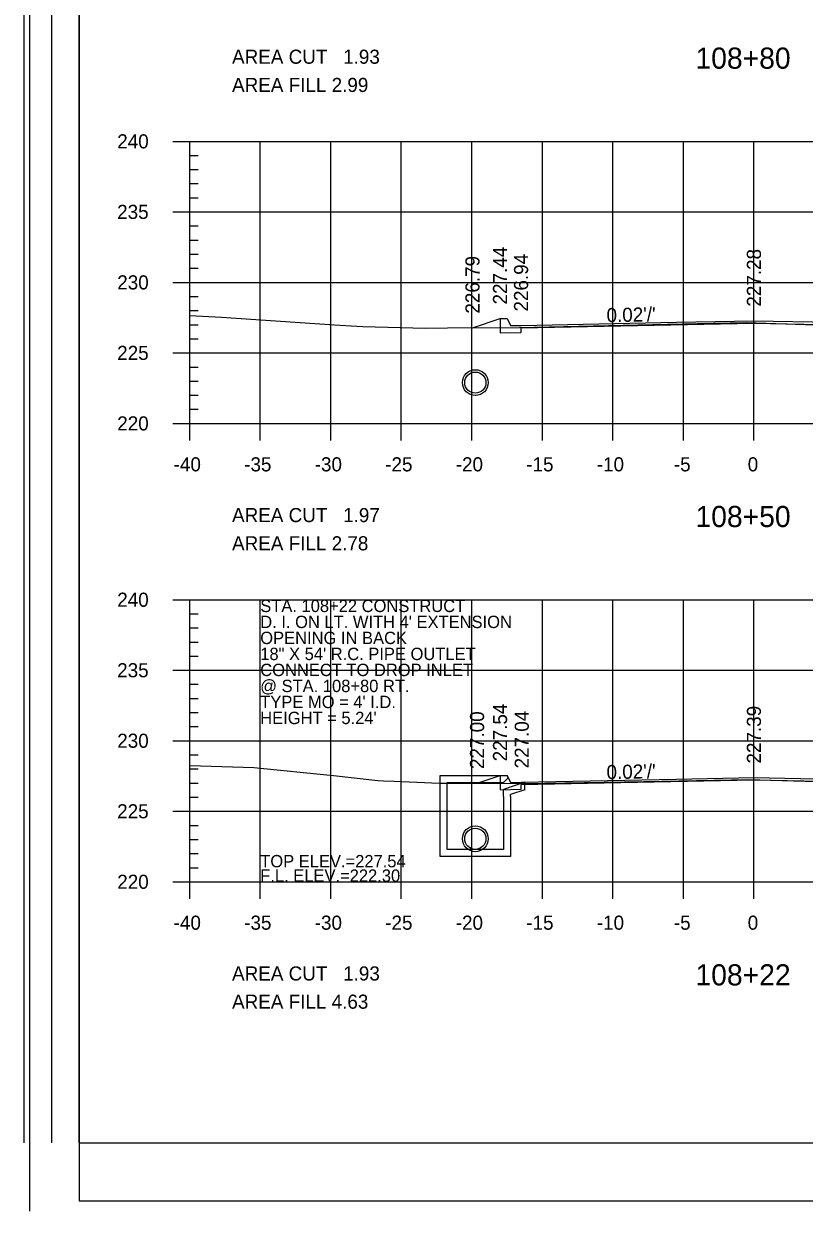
# Model space of a CAD drawing. Extents: x 1367903 to 1373764, y 376865 to 382130.
# Drawn here: x 1371878.7 to 1371989.4, y 377279.1 to 377447.5 of the extents above; entities that cross this region are included whole.
import ezdxf

# ---------------------------------------------------------------- set-up
doc = ezdxf.new("R2010")
doc.units = 0
for name, color, linetype in [('R_Axis', 7, 'Continuous'), ('R_Axis Annot', 7, 'Continuous'), ('R_Border', 7, 'Continuous'), ('R_Border PE', 7, 'Continuous'), ('R_Draft', 7, 'Continuous'), ('R_Exist Surface', 7, 'Continuous'), ('R_Fin Surface', 7, 'Continuous'), ('R_Fin Surface Annot', 7, 'Continuous'), ('R_Grid', 7, 'Continuous'), ('R_Water', 7, 'Continuous'), ('R_Water Annot', 7, 'Continuous')]:
    doc.layers.add(name, color=color, linetype=linetype)

msp = doc.modelspace()

# ---------------------------------------------------------------- linework, layer by layer
for p, q in [((1371937.78, 377340.92), (1371947.28, 377340.92)), ((1371937.78, 377337.92), (1371937.78, 377340.92)), ((1371938.78, 377337.92), (1371938.78, 377339.92)), ((1371938.78, 377339.92), (1371946.78, 377339.92)), ((1371947.44, 377340.59), (1371946.78, 377339.92)), ((1371949.78, 377339.96), (1371946.78, 377338.92)), ((1371947.44, 377340.59), (1371947.28, 377340.92)), ((1371946.78, 377337.92), (1371946.78, 377338.92)), ((1371949.78, 377338.9), (1371947.78, 377338.21)), ((1371947.78, 377337.92), (1371947.78, 377338.21))]:
    msp.add_line(p, q)
for points in [[(1371946.28, 377405.71), (1371946.28, 377405.05), (1371946.28, 377405.05), (1371946.28, 377403.68), (1371949.28, 377403.74), (1371949.28, 377404.41), (1371982.28, 377405.07), (1372015.28, 377404.41), (1372015.28, 377403.74), (1372018.28, 377403.68), (1372018.28, 377405.13), (1372032.28, 377405.41), (1372032.28, 377405.99)], [(1371946.28, 377340.92), (1371946.28, 377340.25), (1371946.28, 377340.25), (1371946.28, 377338.89), (1371949.28, 377338.95), (1371949.28, 377339.62), (1371982.28, 377340.28), (1372015.28, 377339.62), (1372015.28, 377338.95), (1372018.28, 377338.89), (1372018.28, 377340.33), (1372032.28, 377340.61), (1372032.28, 377341.2)], [(1371949.78, 377338.9), (1371949.78, 377339.96)]]:
    msp.add_lwpolyline(points)
at = {"layer": 'R_Axis'}
for p, q in [((1371899.88, 377430.84), (1371904.68, 377430.84)), ((1371902.28, 377390.84), (1371902.28, 377430.84)), ((1371902.28, 377428.84), (1371903.48, 377428.84)), ((1371902.28, 377426.84), (1371903.48, 377426.84)), ((1371902.28, 377424.84), (1371903.48, 377424.84)), ((1371902.28, 377422.84), (1371903.48, 377422.84)), ((1371899.88, 377420.84), (1371904.68, 377420.84)), ((1371902.28, 377418.84), (1371903.48, 377418.84)), ((1371902.28, 377416.84), (1371903.48, 377416.84)), ((1371902.28, 377414.84), (1371903.48, 377414.84)), ((1371902.28, 377412.84), (1371903.48, 377412.84)), ((1371899.88, 377410.84), (1371904.68, 377410.84)), ((1371902.28, 377408.84), (1371903.48, 377408.84)), ((1371902.28, 377406.84), (1371903.48, 377406.84)), ((1371902.28, 377404.84), (1371903.48, 377404.84)), ((1371902.28, 377402.84), (1371903.48, 377402.84)), ((1371899.88, 377400.84), (1371904.68, 377400.84)), ((1371902.28, 377398.84), (1371903.48, 377398.84)), ((1371902.28, 377396.84), (1371903.48, 377396.84)), ((1371902.28, 377394.84), (1371903.48, 377394.84)), ((1371902.28, 377388.44), (1371902.28, 377393.24)), ((1371902.28, 377392.84), (1371903.48, 377392.84)), ((1371912.28, 377388.44), (1371912.28, 377393.24)), ((1371922.28, 377388.44), (1371922.28, 377393.24)), ((1371932.28, 377388.44), (1371932.28, 377393.24)), ((1371942.28, 377388.44), (1371942.28, 377393.24)), ((1371952.28, 377388.44), (1371952.28, 377393.24)), ((1371962.28, 377388.44), (1371962.28, 377393.24)), ((1371972.28, 377388.44), (1371972.28, 377393.24)), ((1371982.28, 377388.44), (1371982.28, 377393.24)), ((1371899.88, 377390.84), (1371904.68, 377390.84)), ((1371902.28, 377390.84), (1372062.28, 377390.84)), ((1371899.88, 377365.84), (1371904.68, 377365.84)), ((1371902.28, 377325.84), (1371902.28, 377365.84)), ((1371902.28, 377363.84), (1371903.48, 377363.84)), ((1371902.28, 377361.84), (1371903.48, 377361.84)), ((1371902.28, 377359.84), (1371903.48, 377359.84)), ((1371902.28, 377357.84), (1371903.48, 377357.84)), ((1371899.88, 377355.84), (1371904.68, 377355.84)), ((1371902.28, 377353.84), (1371903.48, 377353.84)), ((1371902.28, 377351.84), (1371903.48, 377351.84)), ((1371902.28, 377349.84), (1371903.48, 377349.84)), ((1371902.28, 377347.84), (1371903.48, 377347.84)), ((1371899.88, 377345.84), (1371904.68, 377345.84)), ((1371902.28, 377343.84), (1371903.48, 377343.84)), ((1371902.28, 377341.84), (1371903.48, 377341.84)), ((1371902.28, 377339.84), (1371903.48, 377339.84)), ((1371902.28, 377337.84), (1371903.48, 377337.84)), ((1371899.88, 377335.84), (1371904.68, 377335.84)), ((1371902.28, 377333.84), (1371903.48, 377333.84)), ((1371902.28, 377331.84), (1371903.48, 377331.84)), ((1371902.28, 377329.84), (1371903.48, 377329.84)), ((1371902.28, 377323.44), (1371902.28, 377328.24)), ((1371912.28, 377323.44), (1371912.28, 377328.24)), ((1371922.28, 377323.44), (1371922.28, 377328.24)), ((1371932.28, 377323.44), (1371932.28, 377328.24)), ((1371942.28, 377323.44), (1371942.28, 377328.24)), ((1371952.28, 377323.44), (1371952.28, 377328.24)), ((1371962.28, 377323.44), (1371962.28, 377328.24)), ((1371972.28, 377323.44), (1371972.28, 377328.24)), ((1371982.28, 377323.44), (1371982.28, 377328.24)), ((1371902.28, 377327.84), (1371903.48, 377327.84)), ((1371899.88, 377325.84), (1371904.68, 377325.84)), ((1371902.28, 377325.84), (1372062.28, 377325.84))]:
    msp.add_line(p, q, dxfattribs=at)
at = {"layer": 'R_Border'}
for p, q in [((1371879.55, 377620.35), (1371879.55, 377279.12)), ((1371886.58, 377611.47), (1371886.58, 377280.59)), ((1371886.58, 377280.59), (1372090.9, 377280.59))]:
    msp.add_line(p, q, dxfattribs=at)
at = {"layer": 'R_Border PE'}
for p, q in [((1371878.74, 377610.76), (1371878.74, 377288.8)), ((1371882.66, 377610.76), (1371882.66, 377288.8)), ((1371886.58, 377288.8), (1371886.58, 377603.25)), ((1371886.58, 377288.8), (1372090.9, 377288.8))]:
    msp.add_line(p, q, dxfattribs=at)
at = {"layer": 'R_Exist Surface'}
for points in [[(1371902.28, 377406.14), (1371906.78, 377405.89), (1371922.79, 377404.81), (1371925.98, 377404.62), (1371926.84, 377404.58), (1371935.66, 377404.33), (1371938.83, 377404.39), (1371949.02, 377404.45), (1371974.25, 377405), (1371981.24, 377405.14), (1372014.62, 377404), (1372015.78, 377403.97), (1372015.85, 377403.99), (1372017.8, 377404.51), (1372024.3, 377405.15), (1372028.24, 377405.56), (1372038.85, 377406.36), (1372042.42, 377406.71), (1372062.28, 377406.8)], [(1371902.28, 377342.31), (1371911.35, 377342.06), (1371922.67, 377340.92), (1371928.97, 377340.22), (1371929.76, 377340.14), (1371931.25, 377340.09), (1371937.71, 377339.83), (1371942.47, 377339.84), (1371949.84, 377339.76), (1371966.69, 377340.07), (1371981.54, 377340.33), (1372013.23, 377339.4), (1372015.37, 377339.34), (1372015.69, 377339.36), (1372019.46, 377339.64), (1372033.73, 377339.9), (1372035.84, 377340), (1372041.36, 377340.2), (1372042.57, 377340.19), (1372062.28, 377340.77)]]:
    msp.add_lwpolyline(points, dxfattribs=at)
at = {"layer": 'R_Fin Surface'}
for points in [[(1371942.37, 377404.41), (1371946.28, 377405.71), (1371947.28, 377405.71), (1371947.78, 377404.71), (1371949.28, 377404.74), (1371971.28, 377405.18), (1371982.28, 377405.4), (1371993.28, 377405.18), (1372015.28, 377404.74), (1372016.78, 377404.71), (1372017.28, 377405.71), (1372018.28, 377405.71), (1372022.28, 377405.79), (1372032.28, 377405.99), (1372032.58, 377405.89)], [(1371943.02, 377339.83), (1371946.28, 377340.92), (1371947.28, 377340.92), (1371947.78, 377339.92), (1371949.28, 377339.95), (1371971.28, 377340.39), (1371982.28, 377340.61), (1371993.28, 377340.39), (1372015.28, 377339.95), (1372016.78, 377339.92), (1372017.28, 377340.92), (1372018.28, 377340.92), (1372022.28, 377341), (1372032.28, 377341.2), (1372035.87, 377340)]]:
    msp.add_lwpolyline(points, dxfattribs=at)
at = {"layer": 'R_Grid'}
for p, q in [((1371902.28, 377430.84), (1372062.28, 377430.84)), ((1371902.28, 377390.84), (1371902.28, 377430.84)), ((1371912.28, 377390.84), (1371912.28, 377430.84)), ((1371922.28, 377390.84), (1371922.28, 377430.84)), ((1371932.28, 377390.84), (1371932.28, 377430.84)), ((1371942.28, 377390.84), (1371942.28, 377430.84)), ((1371952.28, 377390.84), (1371952.28, 377430.84)), ((1371962.28, 377390.84), (1371962.28, 377430.84)), ((1371972.28, 377390.84), (1371972.28, 377430.84)), ((1371982.28, 377390.84), (1371982.28, 377430.84)), ((1371902.28, 377420.84), (1372062.28, 377420.84)), ((1371902.28, 377410.84), (1372062.28, 377410.84)), ((1371902.28, 377400.84), (1372062.28, 377400.84)), ((1371902.28, 377390.84), (1372062.28, 377390.84)), ((1371902.28, 377365.84), (1372062.28, 377365.84)), ((1371902.28, 377325.84), (1371902.28, 377365.84)), ((1371912.28, 377325.84), (1371912.28, 377365.84)), ((1371922.28, 377325.84), (1371922.28, 377365.84)), ((1371932.28, 377325.84), (1371932.28, 377365.84)), ((1371942.28, 377325.84), (1371942.28, 377365.84)), ((1371952.28, 377325.84), (1371952.28, 377365.84)), ((1371962.28, 377325.84), (1371962.28, 377365.84)), ((1371972.28, 377325.84), (1371972.28, 377365.84)), ((1371982.28, 377325.84), (1371982.28, 377365.84)), ((1371902.28, 377355.84), (1372062.28, 377355.84)), ((1371902.28, 377345.84), (1372062.28, 377345.84)), ((1371902.28, 377335.84), (1372062.28, 377335.84)), ((1371902.28, 377325.84), (1372062.28, 377325.84))]:
    msp.add_line(p, q, dxfattribs=at)
at = {"layer": 'R_Water'}
for p, q in [((1371942.78, 377398.49), (1371942.78, 377398.44)), ((1371942.78, 377398.15), (1371942.78, 377398.11)), ((1371942.78, 377395.15), (1371942.78, 377395.11)), ((1371942.78, 377394.82), (1371942.78, 377394.77))]:
    msp.add_line(p, q, dxfattribs=at)
for points in [[(1371947.78, 377337.92), (1371947.78, 377329.44), (1371942.78, 377329.44), (1371937.78, 377329.44), (1371937.78, 377337.92)], [(1371946.78, 377337.92), (1371946.78, 377330.44), (1371942.78, 377330.44), (1371938.78, 377330.44), (1371938.78, 377337.92)]]:
    msp.add_lwpolyline(points, dxfattribs=at)
for centre, radius in [((1371942.78, 377396.63), 1.83), ((1371942.78, 377396.63), 1.5), ((1371942.78, 377331.94), 1.83), ((1371942.78, 377331.94), 1.83), ((1371942.78, 377331.94), 1.5), ((1371942.78, 377331.94), 1.5)]:
    msp.add_circle(centre, radius, dxfattribs=at)

# ---------------------------------------------------------------- texts
at = {"layer": 'R_Axis Annot'}
for s, height, p in [('AREA CUT   1.93', 2, (1371908.28, 377441.84)), ('108+80', 3, (1371973.99, 377441.14)), ('AREA FILL 2.99', 2, (1371908.28, 377437.84)), ('240', 2, (1371892, 377429.84)), ('235', 2, (1371891.99, 377419.84)), ('230', 2, (1371892, 377409.84)), ('225', 2, (1371891.99, 377399.84)), ('220', 2, (1371892, 377389.84)), ('-40', 2, (1371900, 377384.04)), ('-35', 2, (1371910, 377384.04)), ('-30', 2, (1371920, 377384.04)), ('-25', 2, (1371930, 377384.04)), ('-20', 2, (1371940, 377384.04)), ('-15', 2, (1371950, 377384.04)), ('-10', 2, (1371960, 377384.04)), ('-5', 2, (1371970.93, 377384.04)), ('0', 2, (1371981.4, 377384.04)), ('AREA CUT   1.97', 2, (1371908.28, 377376.84)), ('108+50', 3, (1371973.99, 377376.14)), ('AREA FILL 2.78', 2, (1371908.28, 377372.84)), ('240', 2, (1371892, 377364.84)), ('235', 2, (1371891.99, 377354.84)), ('230', 2, (1371892, 377344.84)), ('225', 2, (1371891.99, 377334.84)), ('220', 2, (1371892, 377324.84)), ('-40', 2, (1371900, 377319.04)), ('-35', 2, (1371910, 377319.04)), ('-30', 2, (1371920, 377319.04)), ('-25', 2, (1371930, 377319.04)), ('-20', 2, (1371940, 377319.04)), ('-15', 2, (1371950, 377319.04)), ('-10', 2, (1371960, 377319.04)), ('-5', 2, (1371970.93, 377319.04)), ('0', 2, (1371981.4, 377319.04)), ('AREA CUT   1.93', 2, (1371908.28, 377311.84)), ('108+22', 3, (1371973.99, 377311.14)), ('AREA FILL 4.63', 2, (1371908.28, 377307.84))]:
    msp.add_text(s, height=height, dxfattribs=at).set_placement(p)
at = {"layer": 'R_Draft'}
for s, p in [('STA. 108+22 CONSTRUCT', (1371912.28, 377364.09)), ("D. I. ON LT. WITH 4' EXTENSION", (1371912.28, 377361.82)), ('OPENING IN BACK', (1371912.28, 377359.55)), ('18" X 54\' R.C. PIPE OUTLET', (1371912.28, 377357.28)), ('CONNECT TO DROP INLET', (1371912.28, 377355.01)), ('@ STA. 108+80 RT.', (1371912.28, 377352.74)), ("TYPE MO = 4' I.D.", (1371912.28, 377350.47)), ("HEIGHT = 5.24'", (1371912.28, 377348.2))]:
    msp.add_text(s, height=1.75, dxfattribs=at).set_placement(p)
at = {"layer": 'R_Fin Surface Annot'}
for s, rotation, p in [('227.44', 90, (1371947.28, 377407.71)), ('226.79', 90, (1371943.37, 377406.41)), ('226.94', 90, (1371950.26, 377406.71)), ('227.28', 90, (1371983.28, 377407.4)), ("0.02'/'", 1.1458, (1371961.4, 377405.19)), ('227.54', 90, (1371947.28, 377342.92)), ('227.04', 90, (1371950.36, 377341.92)), ('227.39', 90, (1371983.28, 377342.61)), ('227.00', 90, (1371944.02, 377341.83)), ("0.02'/'", 1.1458, (1371961.4, 377340.39))]:
    msp.add_text(s, height=2, rotation=rotation, dxfattribs=at).set_placement(p)
at = {"layer": 'R_Water Annot'}
for s, p in [('TOP ELEV.=227.54', (1371912.28, 377327.89)), ('F.L. ELEV.=222.30', (1371912.28, 377325.84))]:
    msp.add_text(s, height=1.75, dxfattribs=at).set_placement(p)

doc.saveas('drawing.dxf')
